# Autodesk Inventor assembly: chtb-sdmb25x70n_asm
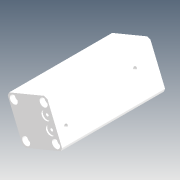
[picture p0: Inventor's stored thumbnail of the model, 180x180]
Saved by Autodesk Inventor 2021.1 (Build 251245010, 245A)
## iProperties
Company: Microsoft
Created: 2018-05
Part Number: chtb-sdmb25x70n_asm
Description: STEP AP214
Document SubType Name: Assembly
Designer: user
Title: chtb-sdmb25x70n_asm.STEP
Author: Windows
Revision Number: ÈÎºÎ
Sending System: SolidWorks 2015
Preprocessor: SwSTEP 2.0
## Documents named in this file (4)
- D:\Vault_2016\Projekty\Clamptek\Hydraulic\CHTB\CHTB-25\Inventor\chtb-sdmb25x70n\chtb-sdmb25x70n_asm.iam
- D:\Vault_2016\Projekty\Clamptek\Hydraulic\CHTB\CHTB-25\Inventor\chtb-sdmb25x70n\CHTB-25QG.ipt
- D:\Vault_2016\Projekty\Clamptek\Hydraulic\CHTB\CHTB-25\Inventor\chtb-sdmb25x70n\CHTB-SDMB25X70NBT.ipt
- D:\Vault_2016\Projekty\Clamptek\Hydraulic\CHTB\CHTB-25\Inventor\chtb-sdmb25x70n\CHTB-SDMB25X70NHSG.ipt
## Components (3 placed, 3 different names)
1. CHTB-25QG_1
2. CHTB-SDMB25X70NBT_2
3. CHTB-SDMB25X70NHSG_3
